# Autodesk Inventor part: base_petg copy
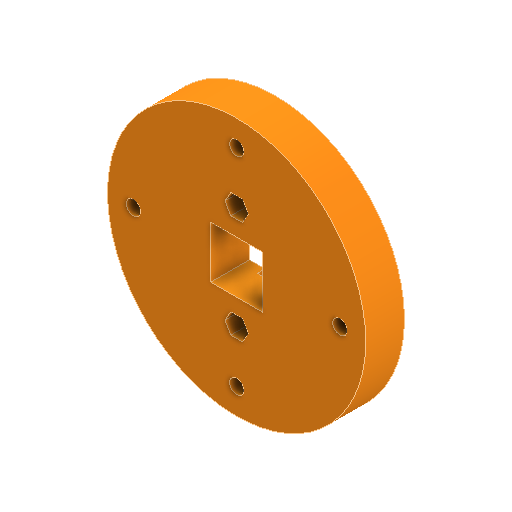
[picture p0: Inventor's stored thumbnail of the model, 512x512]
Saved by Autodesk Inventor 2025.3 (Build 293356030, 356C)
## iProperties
Created: 2025-09
Part Number: base_petg copy
Material: Plastica PET
Document SubType Name: Modeling
Designer: Ryzen5700u
Density: 1.541 g/cm^3
Appearance: Arancione
Author: Ryzen5700u
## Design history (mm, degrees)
sketch "Schizzo1"
  geometry: C1 r 50 at (0, 0); 1 further point
  constraints: 1 centre point, 1 coincident
  dimensions: "d0" = 100 diameter of C1
extrude "Estrusione1" new body sketch "Schizzo1" distance "d1" = 15; taper "d2" = 0 deg
sketch "Schizzo2"
  geometry: 2 further points
  dimensions: "d3" = 40 distance of point (0, 0) point (0, 40)
hole "Foro1" sketch "Schizzo2" at (0, 40) diameter "d4" = 5.5; stored, may be unused: countersink angle "d8" = 90 deg, drill point angle "d10" = 118 deg; dims "d5" = 6, "d6" = 9, "d7" = 4, "d9" = 8
pattern_circular "Serie circolare1" dims angle "d12" = 360 deg
sketch "Schizzo3"
  geometry: L1 (1.8, -17)-(-1.8, -17) reference; L2 (-1.8, 17)-(1.8, 17) reference; L3 (0, 17)-(0, 20); L4 (0, -17)-(0, -20); 3 further points
  constraints: 4 end point, 2 coincident, 2 point on line, 1 perpendicular, 1 vertical
  dimensions: "d14" = 3 distance of L3.start L3.end; "d15" = 3 distance of L4.start L4.end
hole "Foro2" sketch "Schizzo3" at (0, -20), (0, 20) diameter "d16" = 4.5; stored, may be unused: countersink angle "d20" = 90 deg, drill point angle "d22" = 118 deg; dims "d17" = 6, "d18" = 10, "d19" = 5.7, "d21" = 8
sketch "Schizzo4"
  geometry: L1 (-4.5, -20)-(-2.25, -16.103); L2 (-2.25, -16.103)-(2.25, -16.103); L3 (2.25, -16.103)-(4.5, -20); L4 (4.5, -20)-(2.25, -23.897); L5 (2.25, -23.897)-(-2.25, -23.897); L6 (-2.25, -23.897)-(-4.5, -20); L7 (-4.5, 20)-(-2.25, 23.897); L8 (-2.25, 23.897)-(2.25, 23.897); L9 (2.25, 23.897)-(4.5, 20); L10 (4.5, 20)-(2.25, 16.103); L11 (2.25, 16.103)-(-2.25, 16.103); L12 (-2.25, 16.103)-(-4.5, 20); C1 r 2.25 at (0, -20) reference; C2 r 2.25 at (0, 20) reference; 3 further points
  constraints: 24 end point, 2 coincident, 26 other
  dimensions: "d23" = 4.5 distance of L1.end L2.end; "d24" = 4.5 distance of L10.end L11.end
extrude "Estrusione2" cut sketch "Schizzo4" distance "d25" = 7; taper "d26" = 0 deg
sketch "Schizzo5"
  geometry: L1 (10.05, 10.05)-(-10.05, 10.05); L2 (-10.05, 10.05)-(-10.05, -10.05); L3 (-10.05, -10.05)-(10.05, -10.05); L4 (10.05, -10.05)-(10.05, 10.05); L5 (10.05, 10.05)-(-10.05, -10.05); L6 (-10.05, 10.05)-(10.05, -10.05); 1 further point
  constraints: 12 end point, 2 midpoint, 2 parallel, 1 horizontal, 1 perpendicular
  dimensions: "d27" = 20.1 distance of L3.end L2.end; "d28" = 20.1 distance of L2.end L1.end
extrude "Estrusione3" cut sketch "Schizzo5" extent not by distance; stored distance "d29" = 0; taper "d30" = 0 deg
sketch "Schizzo6"
  geometry: L1 (0, -2.636)-(0, -42.758); L2 (-4, -10.05)-(4, -10.05); L3 (4, -10.05)-(4, -28.05); L4 (4, -28.05)-(-4, -28.05); L5 (-4, -28.05)-(-4, -10.05); L6 (10.05, -10.05)-(-10.05, -10.05) reference; 2 further points
  constraints: 10 end point, 3 perpendicular, 2 midpoint, 1 other
  dimensions: "d33" = 8 distance of L3.end L4.end; "d34" = 18 distance of L2.end L3.end
extrude "Estrusione4" cut sketch "Schizzo6" distance "d31" = 3; taper "d32" = 0 deg
mirror "Speculare1"
node "Solido1"
node "Riferimento1"
node "Riferimento2"
